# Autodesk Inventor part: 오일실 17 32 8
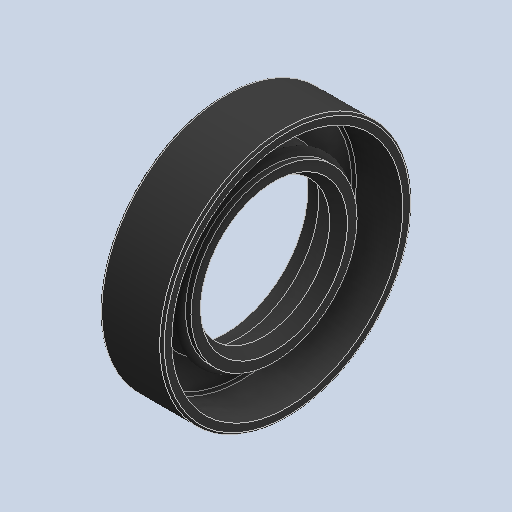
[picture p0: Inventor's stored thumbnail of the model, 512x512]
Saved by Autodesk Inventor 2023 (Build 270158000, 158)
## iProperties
Created: 2024-09
Part Number: 오일실 17 32 8
Material: 고무
Description: 오일-실
Document SubType Name: Modeling
Designer: home
Density: 0.93 g/cm^3
Appearance: 기본값
Author: jhkim
Sending System: Autodesk Inventor 2025
Preprocessor: ST-DEVELOPER v20
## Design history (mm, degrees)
node "오일실 17 32 81"
node "솔리드1"
body "Solid1"
